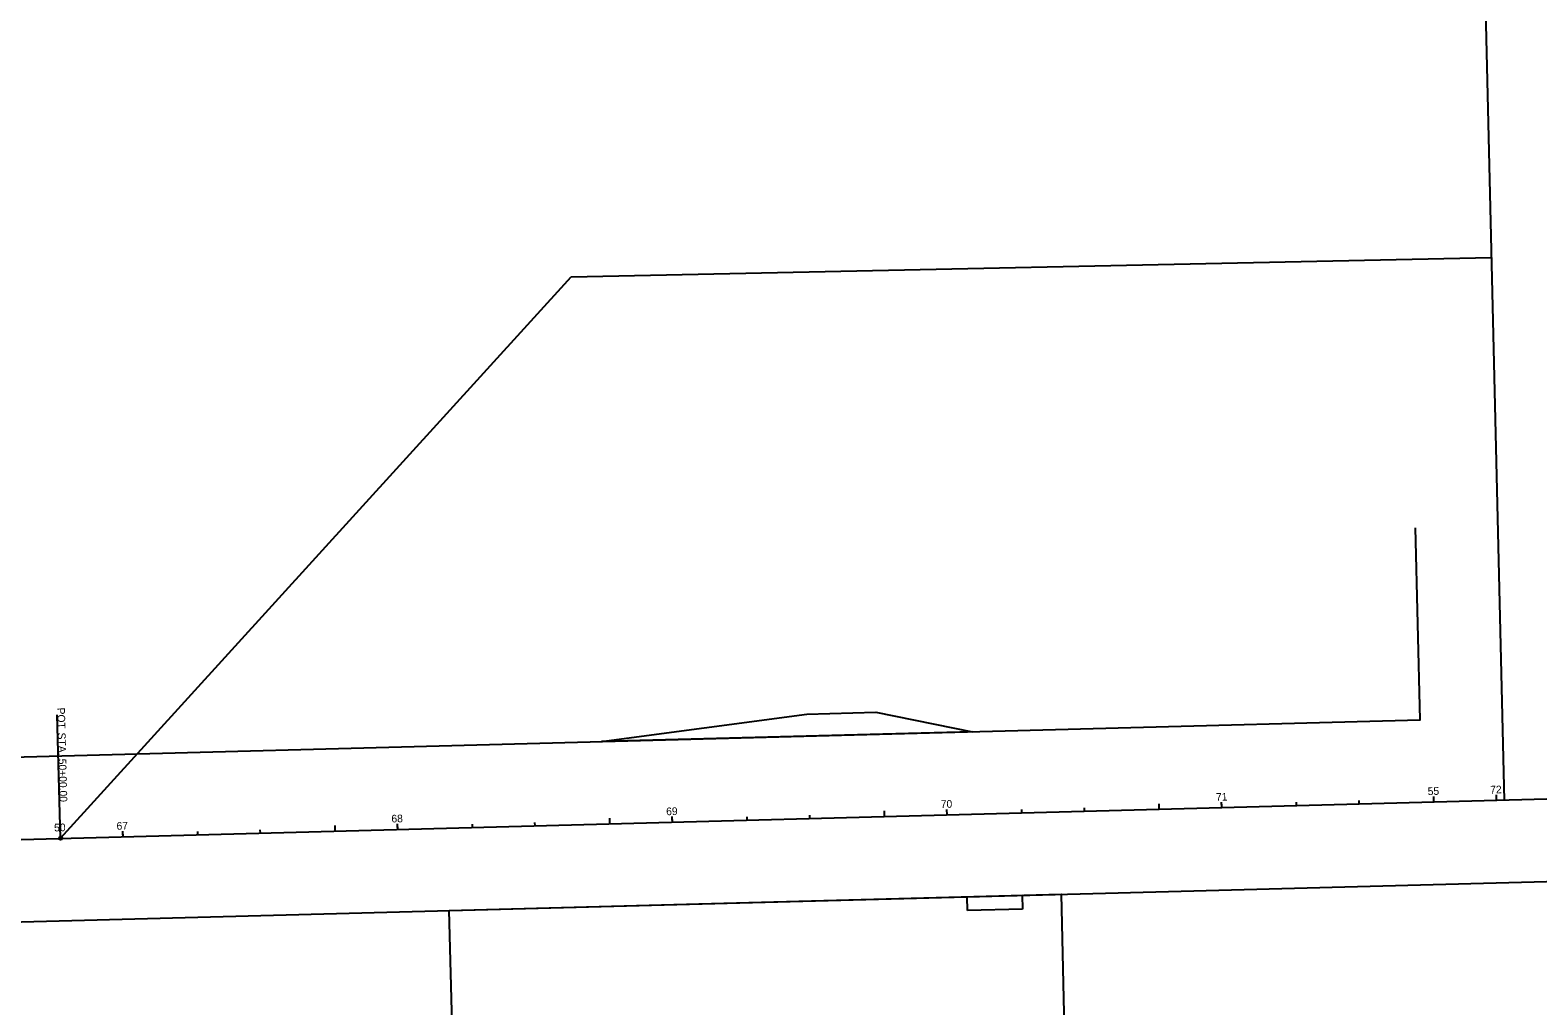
# Model space of a CAD drawing. Extents: x 2402033 to 2407434, y 498266 to 500417.
# Drawn here: x 2403700 to 2404249, y 498624 to 498979 of the extents above; entities that cross this region are included whole.
import ezdxf

# ---------------------------------------------------------------- set-up
doc = ezdxf.new("R2010")
doc.units = 0
for name, color, linetype in [('DR_P_Ditch', 7, 'Continuous'), ('GK_Drainage_Nodes', 7, 'Continuous'), ('PV_P_EOP', 7, 'Continuous'), ('PV_P_Shoulder', 7, 'Continuous'), ('PV_X_COP', 7, 'Continuous'), ('PV_X_EOP', 7, 'Continuous'), ('RD_P_GR_Lt', 7, 'Continuous'), ('SN_X_Public', 7, 'Continuous'), ('UT_X_Cable_TV_FO', 7, 'Continuous'), ('UT_X_Electric_Cells', 7, 'Continuous')]:
    doc.layers.add(name, color=color, linetype=linetype)

msp = doc.modelspace()

# ---------------------------------------------------------------- linework, layer by layer
at = {"layer": 'DR_P_Ditch'}
msp.add_line((2403711.47, 498684.54), (2403710.28, 498729.52), dxfattribs=at)
msp.add_circle((2403711.47, 498684.54), 0.6, dxfattribs=at)
at = {"layer": 'GK_Drainage_Nodes'}
msp.add_line((2403711.47, 498684.54), (2403710.28, 498729.52), dxfattribs=at)
msp.add_circle((2403711.47, 498684.54), 0.6, dxfattribs=at)
at = {"layer": 'PV_P_EOP'}
for p, q in [((2404236.94, 498698.31), (2404213.72, 499677.16)), ((2403004.47, 498665.82), (2407431.7, 498783.04))]:
    msp.add_line(p, q, dxfattribs=at)
at = {"layer": 'PV_P_Shoulder'}
for p, q in [((2404111.33, 498695.13), (2404111.3, 498696.33)), ((2404134.08, 498695.73), (2404134.05, 498696.93)), ((2404211.3, 498697.77), (2404211.24, 498699.77)), ((2404234.04, 498698.37), (2404234.01, 498699.57)), ((2403911.4, 498689.83), (2403911.37, 498691.03)), ((2403934.15, 498690.43), (2403934.12, 498691.63)), ((2404011.37, 498692.48), (2404011.34, 498693.68)), ((2404034.11, 498693.08), (2404034.06, 498695.08)), ((2403711.47, 498684.54), (2403711.42, 498686.54)), ((2403734.22, 498685.14), (2403734.19, 498686.34)), ((2403811.44, 498687.19), (2403811.41, 498688.39)), ((2403834.18, 498687.79), (2403834.15, 498688.99))]:
    msp.add_line(p, q, dxfattribs=at)
at = {"layer": 'PV_X_COP'}
for p, q in [((2403908.35, 498719.76), (2403983.12, 498729.74)), ((2403983.12, 498729.74), (2404008.12, 498730.41)), ((2404008.12, 498730.41), (2404043.31, 498723.34)), ((2404043.31, 498723.34), (2403908.35, 498719.76))]:
    msp.add_line(p, q, dxfattribs=at)
at = {"layer": 'PV_X_EOP'}
for p, q in [((2404041.41, 498663.26), (2404061.41, 498663.79)), ((2404061.41, 498663.79), (2404061.54, 498658.79)), ((2404041.54, 498658.27), (2404041.41, 498663.26)), ((2404061.54, 498658.79), (2404041.54, 498658.27))]:
    msp.add_line(p, q, dxfattribs=at)
at = {"layer": 'RD_P_GR_Lt'}
for p, q in [((2404111.33, 498695.13), (2404111.28, 498697.12)), ((2404134.08, 498695.73), (2404134.02, 498697.73)), ((2404161.31, 498696.45), (2404161.28, 498697.65)), ((2404184.06, 498697.05), (2404184.03, 498698.25)), ((2404211.3, 498697.77), (2404211.24, 498699.77)), ((2404234.04, 498698.37), (2404233.99, 498700.37)), ((2403911.4, 498689.83), (2403911.35, 498691.83)), ((2403934.15, 498690.43), (2403934.09, 498692.43)), ((2403961.38, 498691.16), (2403961.35, 498692.36)), ((2403984.13, 498691.76), (2403984.1, 498692.96)), ((2404011.37, 498692.48), (2404011.31, 498694.48)), ((2404034.11, 498693.08), (2404034.06, 498695.08)), ((2404061.35, 498693.8), (2404061.32, 498695)), ((2404084.09, 498694.4), (2404084.06, 498695.6)), ((2403711.47, 498684.54), (2403711.42, 498686.54)), ((2403734.22, 498685.14), (2403734.16, 498687.14)), ((2403761.45, 498685.86), (2403761.42, 498687.06)), ((2403784.2, 498686.46), (2403784.17, 498687.66)), ((2403811.44, 498687.19), (2403811.38, 498689.18)), ((2403834.18, 498687.79), (2403834.13, 498689.79)), ((2403861.42, 498688.51), (2403861.39, 498689.71)), ((2403884.16, 498689.11), (2403884.13, 498690.31))]:
    msp.add_line(p, q, dxfattribs=at)
at = {"layer": 'SN_X_Public'}
for p, q in [((2404211.3, 498697.77), (2404211.27, 498698.97)), ((2404034.11, 498693.08), (2404034.06, 498695.08)), ((2403711.47, 498684.54), (2403711.42, 498686.54))]:
    msp.add_line(p, q, dxfattribs=at)
at = {"layer": 'UT_X_Cable_TV_FO'}
for p, q in [((2403897.33, 498888.94), (2404232.25, 498895.99)), ((2403711.47, 498684.54), (2403897.33, 498888.94))]:
    msp.add_line(p, q, dxfattribs=at)
msp.add_lwpolyline([(2403852.91, 498658.27), (2404075.62, 498664.17), (2404084.35, 498274.26), (2403863.24, 498268.41)], close=True, dxfattribs=at)
at = {"layer": 'UT_X_Electric_Cells'}
msp.add_line((2403063.62, 498637.38), (2404534.73, 498676.32), dxfattribs=at)
msp.add_lwpolyline([(2403135.11, 498699.29), (2404206.24, 498727.65), (2404204.58, 498797.57)], dxfattribs=at)

# ---------------------------------------------------------------- texts
at = {"layer": 'DR_P_Ditch'}
for s, p in [('POT', (2403710.26, 498732.06)), (' STA. ', (2403710.47, 498724.02)), ('50+00.00', (2403710.75, 498713.45))]:
    msp.add_text(s, height=2.8, rotation=271.5166, dxfattribs=at).set_placement(p)
at = {"layer": 'GK_Drainage_Nodes'}
for s, p in [('POT', (2403710.26, 498732.06)), (' STA. ', (2403710.47, 498724.02)), ('50+00.00', (2403710.75, 498713.45))]:
    msp.add_text(s, height=2.8, rotation=271.5166, dxfattribs=at).set_placement(p)
at = {"layer": 'PV_P_Shoulder'}
for s, p in [('55', (2404209.04, 498700.26)), ('70', (2404031.85, 498695.57)), ('50', (2403709.18, 498687.02))]:
    msp.add_text(s, height=2.8, rotation=1.5166, dxfattribs=at).set_placement(p)
at = {"layer": 'RD_P_GR_Lt'}
for s, p in [('72', (2404231.79, 498700.82)), ('70', (2404031.85, 498695.57)), ('71', (2404131.99, 498698.17)), ('68', (2403831.93, 498690.28)), ('69', (2403931.92, 498692.92)), ('67', (2403731.9, 498687.63))]:
    msp.add_text(s, height=2.8, rotation=1.5166, dxfattribs=at).set_placement(p)
at = {"layer": 'SN_X_Public'}
for s, p in [('70', (2404031.85, 498695.57)), ('50', (2403709.18, 498687.02))]:
    msp.add_text(s, height=2.8, rotation=1.5166, dxfattribs=at).set_placement(p)

doc.saveas('drawing.dxf')
